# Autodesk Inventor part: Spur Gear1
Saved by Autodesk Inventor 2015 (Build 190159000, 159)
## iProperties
Created: 2014-08
Part Number: Spur Gear1
Material: Steel
Document SubType Name: Modeling
Designer: User
Categories: <?xml version="1.0" encoding="UTF-16"?> <MemberInstance><Categories><FamilyTemplate><FamilyTemplateParameter ValueType="xs:double" Id="1" ObjectReferenceKey="da
Density: 1 g/cm^3
Appearance: Steel
CustomPartVersion: 1
Author: User
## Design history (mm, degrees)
sketch "Sketch1"
  geometry: C1 r 6.446 at (0, 0)
  constraints: 1 centre point
  dimensions: "d0" = 12.89292 diameter of C1 (= da_da)
extrude "Extrusion1" new body sketch "Sketch1" distance "d1" = 4 (= da_b); taper "d2" = 0 deg
workplane "Work Plane2"
sketch "Sketch2"
  geometry: C1 r 6.446 at (0, 0) reference; C2 r 5.65 at (0, 0)
  constraints: 1 centre point, 1 coincident
  dimensions: "d3" = 11.3 diameter of C2 (= da_dw)
feature "Pitch Diameter" sketch "Sketch2" dims "d4" = 10, "d5" = 0
workplane "Work Plane8"
workplane "Work Plane9"
feature "Spur Gear" dims "da_b" = 4, "da_d" = 11.48758, "da_aw" = 11.3, "da_da" = 12.89292, "da_df" = 9.30708, "da_dw" = 11.3, angle "da_beta" = 40 deg, "da_lefttooth" = 10, "da_righttooth" = 0
body "Solid1"
body "Srf1"
other parameters: "d16" = 11.3 (= da_aw), "d17" = 0, "d34" = 2.85599 (computed from da_z), "d39" = 0, "d41" = 0, "d43" = 11.3 (= da_aw), "d46" = 11.3 (= da_aw), "d47" = 0, "d48" = 0
